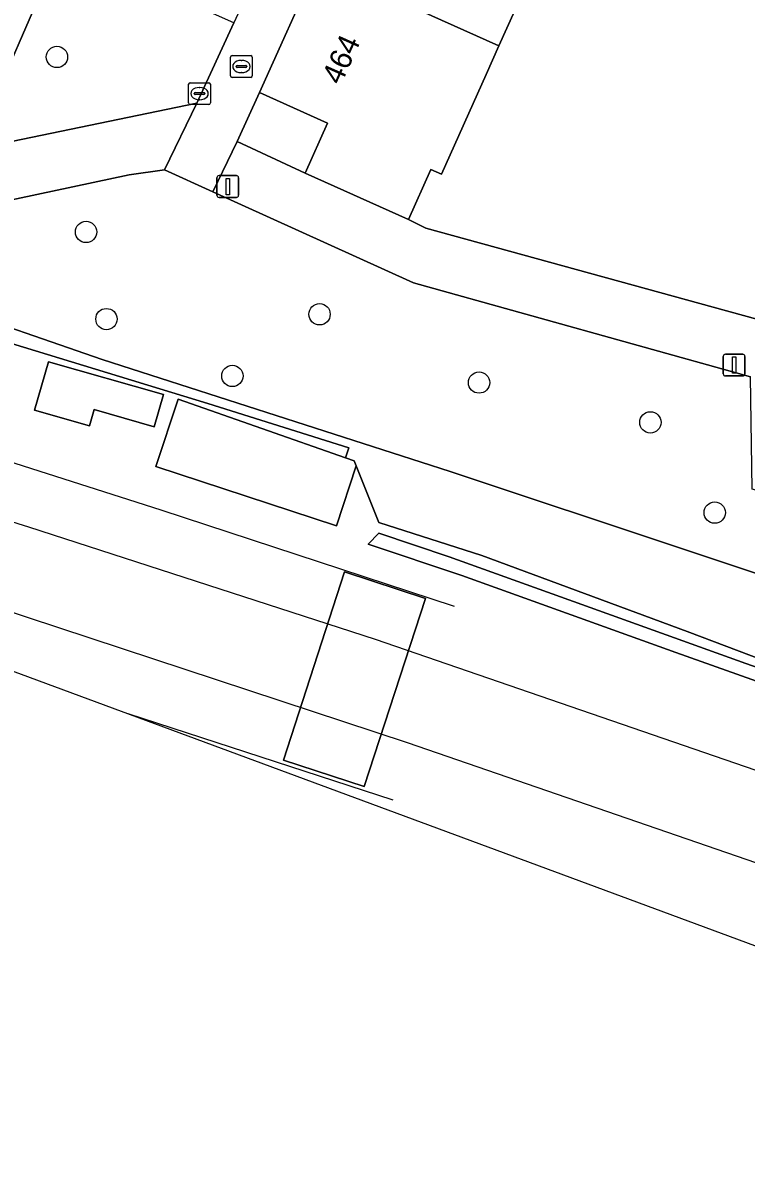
# Model space of a CAD drawing. Extents: x 162989 to 165008, y 383432 to 384338.
# Drawn here: x 163766.9 to 163800.1, y 383839.9 to 383892.6 of the extents above; entities that cross this region are included whole.
import ezdxf

# ---------------------------------------------------------------- set-up
doc = ezdxf.new("R2010")
doc.units = 0
for name, color, linetype in [('IMGEO_Boom', 7, 'Continuous'), ('IMGEO_Brandkraan', 7, 'Continuous'), ('IMGEO_Erf', 7, 'Continuous'), ('IMGEO_Geluidsscherm', 7, 'Continuous'), ('IMGEO_Groenvoorziening', 7, 'Continuous'), ('IMGEO_Hek', 7, 'Continuous'), ('IMGEO_Kolk', 7, 'Continuous'), ('IMGEO_Lichtmast', 7, 'Continuous'), ('IMGEO_Muur', 7, 'Continuous'), ('IMGEO_Pand', 7, 'Continuous'), ('IMGEO_Pand_nummerreeks', 7, 'Continuous'), ('IMGEO_Spoor', 7, 'Continuous'), ('IMGEO_Spoorbaan_gesloten', 7, 'Continuous'), ('IMGEO_Spoorbaan_halfverhard', 7, 'Continuous'), ('IMGEO_Terreindeel_gesloten', 7, 'Continuous'), ('IMGEO_Terreindeel_open', 7, 'Continuous'), ('IMGEO_Voetpad_open', 7, 'Continuous')]:
    doc.layers.add(name, color=color, linetype=linetype)

msp = doc.modelspace()

# ---------------------------------------------------------------- linework, layer by layer
at = {"layer": 'IMGEO_Boom'}
for centre in [(163768.495, 383891.084), (163769.833, 383883.06), (163770.767, 383879.063), (163780.536, 383879.286), (163776.538, 383876.46), (163787.853, 383876.155), (163795.708, 383874.327), (163798.656, 383870.191)]:
    msp.add_circle(centre, 0.489, dxfattribs=at)
at = {"layer": 'IMGEO_Brandkraan'}
for p, q in [((163776.528, 383891.147), (163777.38, 383891.147)), ((163776.453, 383890.221), (163776.453, 383891.073)), ((163776.712, 383890.641), (163776.712, 383890.653)), ((163777.15, 383890.604), (163776.752, 383890.604)), ((163776.755, 383890.69), (163777.153, 383890.69)), ((163776.941, 383890.927), (163776.966, 383890.927)), ((163777.196, 383890.653), (163777.196, 383890.641)), ((163777.454, 383891.073), (163777.454, 383890.221)), ((163777.38, 383890.147), (163776.528, 383890.147)), ((163776.964, 383890.367), (163776.939, 383890.367))]:
    msp.add_line(p, q, dxfattribs=at)
for points in [[(163776.528, 383891.147), (163777.38, 383891.147)], [(163776.453, 383890.221), (163776.453, 383891.073)], [(163777.454, 383891.073), (163777.454, 383890.221)], [(163777.38, 383890.147), (163776.528, 383890.147)]]:
    msp.add_lwpolyline(points, dxfattribs=at)
for centre, radius, start, end in [((163776.53, 383891.071), 0.0765, 91.552, 178.448), ((163776.53, 383891.071), 0.0765, 91.552, 178.448), ((163777.378, 383891.071), 0.0765, 1.552, 88.448), ((163777.378, 383891.071), 0.0765, 1.552, 88.448), ((163776.752, 383890.65), 0.0403, 85.8775, 175.7526), ((163776.749, 383890.64), 0.0366, 178.938, 274.7102), ((163777.153, 383890.647), 0.043, 264.8664, 352.4533), ((163777.157, 383890.652), 0.0386, 1.7309, 96.639), ((163776.53, 383890.223), 0.0765, 181.552, 268.448), ((163776.53, 383890.223), 0.0765, 181.552, 268.448), ((163777.378, 383890.223), 0.0765, 271.552, 358.448), ((163777.378, 383890.223), 0.0765, 271.552, 358.448)]:
    msp.add_arc(centre, radius, start, end, dxfattribs=at)
for centre, major_axis, ratio, start_param, end_param in [((163776.94, 383890.647), (-0.387, 0.002), 0.722429, 4.712389, 7.853982), ((163776.965, 383890.647), (-0.39, 0.002), 0.717154, 1.570796, 4.712389)]:
    msp.add_ellipse(centre, major_axis=major_axis, ratio=ratio, start_param=start_param, end_param=end_param, dxfattribs=at)
at = {"layer": 'IMGEO_Erf'}
msp.add_lwpolyline([(163800.392, 383912.477), (163798.718, 383916.612), (163796.316, 383915.641), (163794.783, 383916.328), (163792.813, 383911.939), (163788.708, 383913.782), (163788.217, 383912.69), (163792.779, 383910.642), (163796.555, 383908.947), (163798.772, 383907.952), (163796.126, 383902.059), (163793.554, 383896.331), (163793.277, 383896.455), (163792.241, 383894.148), (163790.301, 383895.019), (163788.764, 383891.596), (163788.171, 383890.275), (163786.122, 383885.713), (163785.642, 383885.928), (163784.611, 383883.632), (163785.406, 383883.235), (163801.81, 383878.728)], dxfattribs=at)
msp.add_lwpolyline([(163776.763, 383887.208), (163779.876, 383885.758), (163780.905, 383888.05), (163777.782, 383889.452)], close=True, dxfattribs=at)
at = {"layer": 'IMGEO_Geluidsscherm'}
msp.add_lwpolyline([(163774.047, 383875.395), (163781.725, 383872.709), (163782.123, 383872.57), (163783.249, 383869.744), (163787.974, 383868.232), (163797.39, 383864.741), (163802.042, 383862.977), (163811.536, 383859.691), (163820.834, 383856.399), (163836.515, 383850.787), (163850.738, 383845.96), (163855.441, 383844.22), (163861.228, 383841.814), (163878.606, 383834.878)], dxfattribs=at)
at = {"layer": 'IMGEO_Groenvoorziening'}
msp.add_lwpolyline([(163764.618, 383886.843), (163774.913, 383888.97), (163776.604, 383892.642), (163768.685, 383896.176)], close=True, dxfattribs=at)
for points in [[(163898.475, 383851.785), (163861.538, 383848.404), (163817.731, 383863.45), (163809.329, 383871.571), (163807.224, 383869.407), (163800.379, 383871.261), (163800.304, 383876.419), (163784.839, 383880.72), (163775.646, 383884.905), (163773.428, 383885.914), (163771.806, 383885.68), (163763.327, 383883.882), (163761.67, 383880.294), (163761.318, 383879.505), (163762.901, 383879.022), (163763.142, 383879.783), (163770.57, 383877.207), (163786.519, 383872.073), (163829.229, 383857.865), (163846.299, 383851.794), (163880.237, 383839.724)], [(163880.237, 383839.724), (163846.299, 383851.794), (163829.229, 383857.865), (163786.519, 383872.073), (163770.57, 383877.207), (163763.142, 383879.783), (163762.901, 383879.022), (163775.421, 383875.198), (163781.885, 383873.168), (163781.725, 383872.709), (163782.123, 383872.57), (163782.214, 383872.341), (163783.249, 383869.744), (163787.974, 383868.232), (163797.39, 383864.741), (163802.042, 383862.977), (163811.536, 383859.691), (163820.834, 383856.399), (163836.515, 383850.787), (163850.738, 383845.96), (163855.441, 383844.22), (163861.228, 383841.814), (163878.606, 383834.878)]]:
    msp.add_lwpolyline(points, dxfattribs=at)
at = {"layer": 'IMGEO_Hek'}
for points in [[(163786.726, 383865.892), (163773.267, 383870.305), (163761.346, 383874.116), (163761.892, 383875.837), (163762.901, 383879.022), (163775.421, 383875.198), (163781.885, 383873.168), (163781.725, 383872.709)], [(163771.745, 383860.975), (163783.89, 383857.018)]]:
    msp.add_lwpolyline(points, dxfattribs=at)
at = {"layer": 'IMGEO_Kolk'}
for p, q in [((163774.534, 383888.977), (163774.534, 383889.829)), ((163774.609, 383889.903), (163775.461, 383889.903)), ((163775.022, 383889.683), (163775.047, 383889.683)), ((163775.535, 383889.829), (163775.535, 383888.977)), ((163774.793, 383889.397), (163774.793, 383889.409)), ((163775.231, 383889.36), (163774.833, 383889.36)), ((163774.836, 383889.446), (163775.234, 383889.446)), ((163775.045, 383889.123), (163775.02, 383889.123)), ((163775.277, 383889.409), (163775.277, 383889.397)), ((163775.461, 383888.903), (163774.609, 383888.903))]:
    msp.add_line(p, q, dxfattribs=at)
for points in [[(163774.534, 383888.977), (163774.534, 383889.829)], [(163774.609, 383889.903), (163775.461, 383889.903)], [(163775.535, 383889.829), (163775.535, 383888.977)], [(163775.461, 383888.903), (163774.609, 383888.903)]]:
    msp.add_lwpolyline(points, dxfattribs=at)
for centre, radius, start, end in [((163774.611, 383889.827), 0.0765, 91.552, 178.448), ((163774.611, 383889.827), 0.0765, 91.552, 178.448), ((163775.459, 383889.827), 0.0765, 1.552, 88.448), ((163775.459, 383889.827), 0.0765, 1.552, 88.448), ((163774.611, 383888.979), 0.0765, 181.552, 268.448), ((163774.611, 383888.979), 0.0765, 181.552, 268.448), ((163774.833, 383889.406), 0.0403, 85.8775, 175.7526), ((163774.83, 383889.396), 0.0366, 178.938, 274.7102), ((163775.234, 383889.403), 0.043, 264.8664, 352.4533), ((163775.238, 383889.408), 0.0386, 1.7309, 96.639), ((163775.459, 383888.979), 0.0765, 271.552, 358.448), ((163775.459, 383888.979), 0.0765, 271.552, 358.448)]:
    msp.add_arc(centre, radius, start, end, dxfattribs=at)
for centre, major_axis, ratio, start_param, end_param in [((163775.021, 383889.403), (-0.387, 0.002), 0.722429, 4.712389, 7.853982), ((163775.046, 383889.403), (-0.39, 0.002), 0.717154, 1.570796, 4.712389)]:
    msp.add_ellipse(centre, major_axis=major_axis, ratio=ratio, start_param=start_param, end_param=end_param, dxfattribs=at)
at = {"layer": 'IMGEO_Lichtmast'}
for p, q in [((163775.834, 383884.742), (163775.834, 383885.542)), ((163775.834, 383885.542), (163775.834, 383884.742)), ((163775.934, 383885.642), (163776.724, 383885.642)), ((163776.724, 383885.642), (163775.934, 383885.642)), ((163776.824, 383885.542), (163776.824, 383884.742)), ((163776.824, 383884.742), (163776.824, 383885.542)), ((163776.724, 383884.642), (163775.934, 383884.642)), ((163775.934, 383884.642), (163776.724, 383884.642)), ((163799.149, 383877.456), (163799.939, 383877.456)), ((163799.939, 383877.456), (163799.149, 383877.456)), ((163799.049, 383876.556), (163799.049, 383877.356)), ((163799.049, 383877.356), (163799.049, 383876.556)), ((163800.039, 383877.356), (163800.039, 383876.556)), ((163800.039, 383876.556), (163800.039, 383877.356)), ((163799.939, 383876.456), (163799.149, 383876.456)), ((163799.149, 383876.456), (163799.939, 383876.456))]:
    msp.add_line(p, q, dxfattribs=at)
for points in [[(163776.254, 383885.517), (163776.404, 383885.517), (163776.404, 383884.767), (163776.254, 383884.767), (163776.254, 383885.517)], [(163799.469, 383877.331), (163799.619, 383877.331), (163799.619, 383876.581), (163799.469, 383876.581), (163799.469, 383877.331)]]:
    msp.add_lwpolyline(points, dxfattribs=at)
for centre, start, end in [((163775.934, 383885.542), 90, 180), ((163775.934, 383885.542), 90, 180), ((163776.724, 383885.542), 0, 90), ((163776.724, 383885.542), 360, 90), ((163775.934, 383884.742), 180, 270), ((163775.934, 383884.742), 180, 270), ((163776.724, 383884.742), 270, 0), ((163776.724, 383884.742), 270, 0), ((163799.149, 383877.356), 90, 180), ((163799.149, 383877.356), 90, 180), ((163799.939, 383877.356), 0, 90), ((163799.939, 383877.356), 360, 90), ((163799.149, 383876.556), 180, 270), ((163799.149, 383876.556), 180, 270), ((163799.939, 383876.556), 270, 0), ((163799.939, 383876.556), 270, 0)]:
    msp.add_arc(centre, 0.1, start, end, dxfattribs=at)
at = {"layer": 'IMGEO_Muur'}
msp.add_lwpolyline([(163805.759, 383880.271), (163801.81, 383878.728), (163785.406, 383883.235), (163784.611, 383883.632)], dxfattribs=at)
at = {"layer": 'IMGEO_Pand'}
for points in [[(163782.999, 383901.07), (163780.426, 383895.34), (163788.764, 383891.596), (163790.301, 383895.019), (163792.241, 383894.148), (163793.277, 383896.455)], [(163788.764, 383891.596), (163780.426, 383895.34), (163777.782, 383889.452), (163780.905, 383888.05), (163779.876, 383885.758), (163784.611, 383883.632), (163785.642, 383885.928), (163786.122, 383885.713), (163788.171, 383890.275)]]:
    msp.add_lwpolyline(points, close=True, dxfattribs=at)
at = {"layer": 'IMGEO_Spoor'}
for points in [[(163666.504, 383898.782), (163711.098, 383886.583), (163738.85, 383878.416), (163767.191, 383869.544), (163783.087, 383864.395), (163809.961, 383855.143), (163826.892, 383849.133), (163844.814, 383842.61), (163875.401, 383830.856)], [(163680.538, 383891), (163718.441, 383880.353), (163738.829, 383874.363), (163758.351, 383868.284), (163784.552, 383859.656), (163812.02, 383850.197), (163835.796, 383841.636), (163859.382, 383832.867)]]:
    msp.add_lwpolyline(points, dxfattribs=at)
at = {"layer": 'IMGEO_Spoorbaan_gesloten'}
msp.add_lwpolyline([(163778.878, 383858.842), (163782.581, 383857.628), (163785.394, 383866.254), (163781.675, 383867.475)], close=True, dxfattribs=at)
at = {"layer": 'IMGEO_Spoorbaan_halfverhard'}
for points in [[(163802.042, 383862.977), (163797.39, 383864.741), (163787.974, 383868.232), (163783.249, 383869.744), (163782.214, 383872.341), (163781.311, 383869.592), (163773.034, 383872.311), (163774.047, 383875.395), (163781.725, 383872.709), (163781.885, 383873.168), (163775.421, 383875.198), (163762.901, 383879.022)], [(163864.152, 383839.494), (163854.515, 383843.287), (163852.121, 383844.294), (163845.11, 383846.729), (163832.424, 383851.195), (163815.197, 383857.267), (163796.878, 383863.779), (163787.055, 383867.312), (163782.762, 383868.752), (163783.261, 383869.243), (163786.475, 383868.16), (163792.556, 383865.978), (163800.087, 383863.28), (163808.79, 383860.202), (163819.561, 383856.383), (163826.91, 383853.804), (163837.203, 383850.176), (163846.239, 383846.996), (163859.103, 383842.175), (163867.653, 383838.805)], [(163759.195, 383865.619), (163829.513, 383839.601)]]:
    msp.add_lwpolyline(points, dxfattribs=at)
for points in [[(163772.957, 383874.128), (163770.203, 383874.914), (163769.992, 383874.173), (163767.473, 383874.892), (163768.105, 383877.107), (163773.378, 383875.603)], [(163782.581, 383857.628), (163778.878, 383858.842), (163781.675, 383867.475), (163785.394, 383866.254)]]:
    msp.add_lwpolyline(points, close=True, dxfattribs=at)
at = {"layer": 'IMGEO_Terreindeel_gesloten'}
msp.add_lwpolyline([(163867.653, 383838.805), (163859.103, 383842.175), (163846.239, 383846.996), (163837.203, 383850.176), (163826.91, 383853.804), (163819.561, 383856.383), (163808.79, 383860.202), (163800.087, 383863.28), (163792.556, 383865.978), (163786.475, 383868.16), (163783.261, 383869.243), (163782.762, 383868.752), (163787.055, 383867.312), (163796.878, 383863.779), (163815.197, 383857.267), (163832.424, 383851.195), (163845.11, 383846.729), (163852.121, 383844.294), (163854.515, 383843.287), (163864.152, 383839.494)], dxfattribs=at)
at = {"layer": 'IMGEO_Terreindeel_open'}
for points in [[(163768.105, 383877.107), (163767.473, 383874.892), (163769.992, 383874.173), (163770.203, 383874.914), (163772.957, 383874.128), (163773.378, 383875.603)], [(163781.725, 383872.709), (163774.047, 383875.395), (163773.034, 383872.311), (163781.311, 383869.592), (163782.214, 383872.341), (163782.123, 383872.57)]]:
    msp.add_lwpolyline(points, close=True, dxfattribs=at)
at = {"layer": 'IMGEO_Voetpad_open'}
for points in [[(163796.207, 383937.605), (163795.81, 383936.718), (163791.052, 383926.094), (163779.619, 383900.563), (163778.471, 383898), (163778.968, 383897.775), (163776.604, 383892.642), (163774.913, 383888.97), (163773.428, 383885.914), (163775.646, 383884.905), (163776.763, 383887.208), (163777.782, 383889.452), (163780.426, 383895.34), (163782.999, 383901.07), (163785.571, 383906.798), (163788.217, 383912.69), (163788.708, 383913.782), (163793.673, 383924.841)], [(163761.346, 383888.133), (163759.16, 383883.306), (163755.541, 383874.377), (163757.903, 383873.647), (163758.779, 383876.374), (163759.782, 383876.052), (163760.054, 383876.662), (163761.318, 383879.505), (163761.67, 383880.294), (163763.327, 383883.882), (163764.618, 383886.843), (163768.685, 383896.176), (163770.135, 383899.504), (163772.036, 383903.853), (163783.211, 383929.241)], [(163801.81, 383878.728), (163785.406, 383883.235), (163784.611, 383883.632), (163779.876, 383885.758), (163776.763, 383887.208), (163775.646, 383884.905), (163784.839, 383880.72), (163800.304, 383876.419)]]:
    msp.add_lwpolyline(points, dxfattribs=at)
msp.add_lwpolyline([(163774.913, 383888.97), (163764.618, 383886.843), (163763.327, 383883.882), (163771.806, 383885.68), (163773.428, 383885.914)], close=True, dxfattribs=at)

# ---------------------------------------------------------------- texts
at = {"layer": 'IMGEO_Pand_nummerreeks'}
msp.add_text('464', height=1, rotation=65.8157, dxfattribs=at).set_placement((163781.514, 383889.757))

doc.saveas('drawing.dxf')
